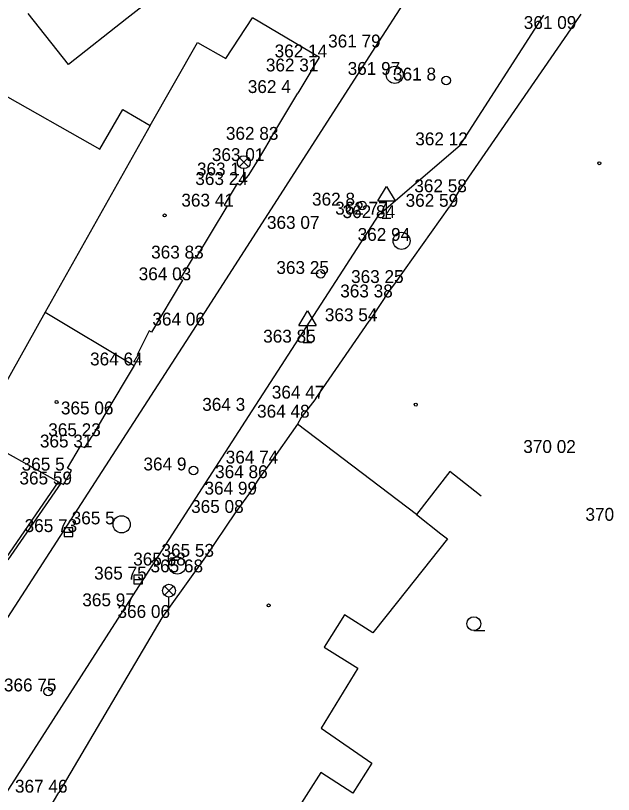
# Model space of a CAD drawing. Extents: x -688316 to -688024, y -973785 to -973591.
# Drawn here: x -688087.33 to -688052.43, y -973675.68 to -973630.22 of the extents above; entities that cross this region are included whole.
import ezdxf

# ---------------------------------------------------------------- set-up
doc = ezdxf.new("R2010")
doc.units = 0
for name, color, linetype in [('Vrstva 10', 7, 'Continuous'), ('Vrstva 27', 7, 'Continuous'), ('Vrstva 28_Verejne osvetleni', 7, 'Continuous'), ('Vrstva 3', 7, 'Continuous'), ('Vrstva 33', 7, 'Continuous'), ('Vrstva 34', 7, 'Continuous'), ('Vrstva 36', 7, 'Continuous'), ('Vrstva 5', 7, 'Continuous'), ('Vrstva 58', 7, 'Continuous'), ('Vrstva 6', 7, 'Continuous'), ('Vrstva 9', 7, 'Continuous')]:
    doc.layers.add(name, color=color, linetype=linetype)

# ---------------------------------------------------------------- blocks, each defined once
blk = doc.blocks.new('B_NESP')
at = {"layer": 'Vrstva 58'}
blk.add_circle((0, 0), 0.875, dxfattribs=at)
blk = doc.blocks.new('DZ')
at = {"layer": 'Vrstva 34'}
for p, q in [((-5, 10), (0, 18.5)), ((0, 18.5), (5, 10)), ((-5, 10), (5, 10)), ((0, 0), (0, 10)), ((-2.49, 0), (2.49, 0))]:
    blk.add_line(p, q, dxfattribs=at)
blk = doc.blocks.new('LAO')
at = {"layer": 'Vrstva 33'}
for p, q in [((-2.65, 14.16), (2.65, 8.85)), ((-2.65, 8.85), (2.65, 14.16)), ((0, 0), (0, 7.75))]:
    blk.add_line(p, q, dxfattribs=at)
blk.add_circle((0, 11.5), 3.75, dxfattribs=at)
blk = doc.blocks.new('SAK')
at = {"layer": 'Vrstva 27'}
blk.add_circle((0, 0), 5, dxfattribs=at)
blk = doc.blocks.new('SV')
at = {"layer": 'Vrstva 28_Verejne osvetleni'}
blk.add_circle((0, 0), 2.5, dxfattribs=at)
blk = doc.blocks.new('ZAHRA')
at = {"layer": 'Vrstva 36'}
blk.add_line((-0.12, 0), (6.38, 0.03), dxfattribs=at)
blk.add_circle((-0.12, 4.03), 4.03, dxfattribs=at)
blk = doc.blocks.new('VP')
at = {"layer": 'Vrstva 27'}
blk.add_line((-2.5, 0), (2.5, 0), dxfattribs=at)
blk.add_lwpolyline([(-2.5, -2.5), (2.5, -2.5), (2.5, 2.5), (-2.5, 2.5)], close=True, dxfattribs=at)

msp = doc.modelspace()

# ---------------------------------------------------------------- linework, layer by layer
at = {"layer": 'Vrstva 10'}
for p, q in [((-688066.34, -973632.08), (-688059.63, -973621.62)), ((-688061.38, -973637.79), (-688056.49, -973630.19)), ((-688076.78, -973648.31), (-688066.34, -973632.08)), ((-688066.11, -973641.84), (-688061.38, -973637.79)), ((-688073.52, -973653.29), (-688066.11, -973641.84)), ((-688089.26, -973667.62), (-688076.78, -973648.31)), ((-688080.87, -973664.7), (-688073.52, -973653.29)), ((-688087.77, -973662), (-688084.68, -973657.51)), ((-688088.66, -973676.81), (-688080.87, -973664.7))]:
    msp.add_line(p, q, dxfattribs=at)
at = {"layer": 'Vrstva 5'}
for p, q in [((-688079.01, -973628.96), (-688080.84, -973630.4)), ((-688084.25, -973633.08), (-688086.6, -973630.1)), ((-688080.84, -973630.4), (-688084.25, -973633.08)), ((-688075.06, -973632.73), (-688073.51, -973630.36)), ((-688054.92, -973631), (-688061.49, -973640.53)), ((-688079.48, -973636.64), (-688076.72, -973631.79)), ((-688076.72, -973631.79), (-688075.06, -973632.73)), ((-688089.95, -973633.75), (-688082.42, -973638.02)), ((-688072.49, -973637.47), (-688070.86, -973634.74)), ((-688082.42, -973638.02), (-688081.07, -973635.7)), ((-688081.07, -973635.7), (-688079.48, -973636.64)), ((-688085.61, -973647.54), (-688080.41, -973650.64)), ((-688069.81, -973652.58), (-688066.69, -973648.06)), ((-688063.93, -973659.35), (-688070.88, -973654.07)), ((-688061.98, -973656.84), (-688063.93, -973659.35)), ((-688060.53, -973657.98), (-688061.98, -973656.84)), ((-688060.15, -973658.28), (-688060.53, -973657.98)), ((-688063.93, -973659.35), (-688062.5, -973660.47)), ((-688062.5, -973660.47), (-688062.12, -973660.76)), ((-688062.12, -973660.76), (-688065.04, -973664.45)), ((-688065.04, -973664.45), (-688066.47, -973666.25)), ((-688067.35, -973668.31), (-688069.49, -973671.81)), ((-688069.49, -973671.81), (-688066.53, -973673.86)), ((-688066.53, -973673.86), (-688067.65, -973675.61)), ((-688069.52, -973674.41), (-688070.24, -973675.54)), ((-688067.65, -973675.61), (-688069.52, -973674.41)), ((-688070.24, -973675.54), (-688071.06, -973676.81))]:
    msp.add_line(p, q, dxfattribs=at)
for points in [[(-688070.09, -973633.48), (-688069.59, -973632.66), (-688073.51, -973630.36)], [(-688079.48, -973636.64), (-688085.61, -973647.54), (-688089.66, -973654.75)], [(-688073.23, -973638.71), (-688073.75, -973639.55), (-688074.25, -973640.11), (-688074.39, -973640.02), (-688075.15, -973641.29), (-688075.01, -973641.37), (-688076.83, -973644.4), (-688076.97, -973644.33), (-688077.73, -973645.58), (-688077.58, -973645.67), (-688079.39, -973648.7), (-688079.53, -973648.63), (-688080.23, -973650.02), (-688080.09, -973650.1), (-688080.41, -973650.64), (-688082.12, -973653.5)], [(-688065.78, -973646.67), (-688065.6, -973646.42), (-688065.16, -973645.83), (-688062, -973641.38)], [(-688099.29, -973649.41), (-688099.15, -973649.49), (-688090.01, -973654.56), (-688089.66, -973654.75), (-688084.82, -973657.44), (-688084.68, -973657.51), (-688084.54, -973657.59), (-688084.06, -973656.78), (-688084.31, -973656.63), (-688083.55, -973655.36), (-688083.28, -973655.43), (-688082.86, -973654.77)], [(-688070.67, -973653.69), (-688070.88, -973654.07), (-688072.5, -973656.37)], [(-688073.12, -973657.22), (-688073.74, -973658.18), (-688074.52, -973659.25), (-688076.25, -973661.81)], [(-688076.88, -973662.72), (-688078.8, -973665.38), (-688084.8, -973675.58)], [(-688066.47, -973666.25), (-688068.13, -973665.21), (-688069.31, -973667.08), (-688067.35, -973668.31)]]:
    msp.add_lwpolyline(points, dxfattribs=at)
at = {"layer": 'Vrstva 6'}
for p, q in [((-688054.34, -973630.14), (-688054.92, -973631)), ((-688070.09, -973633.48), (-688070.86, -973634.74)), ((-688072.49, -973637.47), (-688073.23, -973638.71)), ((-688061.49, -973640.53), (-688062, -973641.38)), ((-688065.78, -973646.67), (-688066.69, -973648.06)), ((-688069.81, -973652.58), (-688070.67, -973653.69)), ((-688082.12, -973653.5), (-688082.86, -973654.77)), ((-688072.5, -973656.37), (-688073.12, -973657.22)), ((-688076.25, -973661.81), (-688076.88, -973662.72)), ((-688085.38, -973676.52), (-688084.8, -973675.58))]:
    msp.add_line(p, q, dxfattribs=at)
at = {"layer": 'Vrstva 9'}
msp.add_lwpolyline([(-688088.82, -973663.21), (-688087.9, -973661.91), (-688084.82, -973657.44)], dxfattribs=at)

# ---------------------------------------------------------------- block references
at = {"layer": 'Vrstva 27', "xscale": 0.1, "yscale": 0.10000000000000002}
for name, p in [('SAK', (-688065.2, -973633.68)), ('SAK', (-688064.8, -973643.37)), ('SAK', (-688081.14, -973659.92)), ('VP', (-688084.24, -973660.37)), ('SAK', (-688077.89, -973662.32)), ('VP', (-688080.18, -973663.14))]:
    msp.add_blockref(name, p, dxfattribs=at)
at = {"layer": 'Vrstva 28_Verejne osvetleni', "xscale": 0.1, "yscale": 0.10000000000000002}
for p in [(-688062.2, -973634.01), (-688067.11, -973641.31), (-688069.52, -973645.3), (-688076.95, -973656.77), (-688085.43, -973669.67)]:
    msp.add_blockref('SV', p, dxfattribs=at)
at = {"layer": 'Vrstva 33', "xscale": 0.1, "yscale": 0.10000000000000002}
for p in [(-688074.01, -973639.93), (-688078.38, -973664.94)]:
    msp.add_blockref('LAO', p, dxfattribs=at)
at = {"layer": 'Vrstva 34', "xscale": 0.1, "yscale": 0.10000000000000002}
for p in [(-688065.68, -973642.04), (-688065.68, -973642.04), (-688065.68, -973642.04), (-688065.68, -973642.04), (-688070.29, -973649.31), (-688070.29, -973649.31), (-688070.29, -973649.31), (-688070.29, -973649.31)]:
    msp.add_blockref('DZ', p, dxfattribs=at)
at = {"layer": 'Vrstva 36', "xscale": 0.1, "yscale": 0.10000000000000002}
msp.add_blockref('ZAHRA', (-688060.57, -973666.12), dxfattribs=at)
at = {"layer": 'Vrstva 58', "xscale": 0.1, "yscale": 0.10000000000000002}
for p in [(-688053.26, -973638.84), (-688053.26, -973638.84), (-688053.26, -973638.84), (-688053.26, -973638.84), (-688078.63, -973641.89), (-688078.63, -973641.89), (-688078.63, -973641.89), (-688078.63, -973641.89), (-688084.94, -973652.78), (-688084.94, -973652.78), (-688084.94, -973652.78), (-688084.94, -973652.78), (-688063.97, -973652.93), (-688063.97, -973652.93), (-688063.97, -973652.93), (-688063.97, -973652.93), (-688072.56, -973664.65), (-688072.56, -973664.65), (-688072.56, -973664.65), (-688072.56, -973664.65)]:
    msp.add_blockref('B_NESP', p, dxfattribs=at)

# ---------------------------------------------------------------- texts
at = {"layer": 'Vrstva 3'}
for s, p in [('361 09 ', (-688057.668, -973631)), ('361 09 ', (-688057.668, -973631)), ('361 09 ', (-688057.668, -973631)), ('361 09 ', (-688057.668, -973631)), ('361 09 ', (-688057.668, -973631)), ('361 09 ', (-688057.668, -973631)), ('361 09 ', (-688057.668, -973631)), ('361 79 ', (-688069.088, -973632.08)), ('361 79 ', (-688069.088, -973632.08)), ('361 79 ', (-688069.088, -973632.08)), ('361 79 ', (-688069.088, -973632.08)), ('361 79 ', (-688069.088, -973632.08)), ('361 79 ', (-688069.088, -973632.08)), ('361 79 ', (-688069.088, -973632.08)), ('362 14 ', (-688072.211, -973632.66)), ('362 14 ', (-688072.211, -973632.66)), ('362 14 ', (-688072.211, -973632.66)), ('362 14 ', (-688072.211, -973632.66)), ('362 14 ', (-688072.211, -973632.66)), ('362 14 ', (-688072.211, -973632.66)), ('362 14 ', (-688072.211, -973632.66)), ('362 31 ', (-688072.723, -973633.48)), ('362 31 ', (-688072.723, -973633.48)), ('362 31 ', (-688072.723, -973633.48)), ('362 31 ', (-688072.723, -973633.48)), ('362 31 ', (-688072.723, -973633.48)), ('362 31 ', (-688072.723, -973633.48)), ('362 31 ', (-688072.723, -973633.48)), ('361 97 ', (-688067.948, -973633.68)), ('361 97 ', (-688067.948, -973633.68)), ('361 97 ', (-688067.948, -973633.68)), ('361 97 ', (-688067.948, -973633.68)), ('361 97 ', (-688067.948, -973633.68)), ('361 97 ', (-688067.948, -973633.68)), ('361 97 ', (-688067.948, -973633.68)), ('361 8  ', (-688065.299, -973634.01)), ('361 8  ', (-688065.299, -973634.01)), ('361 8  ', (-688065.299, -973634.01)), ('361 8  ', (-688065.299, -973634.01)), ('361 8  ', (-688065.299, -973634.01)), ('361 8  ', (-688065.299, -973634.01)), ('361 8  ', (-688065.299, -973634.01)), ('362 4  ', (-688073.777, -973634.74)), ('362 4  ', (-688073.777, -973634.74)), ('362 4  ', (-688073.777, -973634.74)), ('362 4  ', (-688073.777, -973634.74)), ('362 4  ', (-688073.777, -973634.74)), ('362 4  ', (-688073.777, -973634.74)), ('362 4  ', (-688073.777, -973634.74)), ('362 83 ', (-688075.056, -973637.47)), ('362 83 ', (-688075.056, -973637.47)), ('362 83 ', (-688075.056, -973637.47)), ('362 83 ', (-688075.056, -973637.47)), ('362 83 ', (-688075.056, -973637.47)), ('362 83 ', (-688075.056, -973637.47)), ('362 83 ', (-688075.056, -973637.47)), ('362 12 ', (-688064.001, -973637.79)), ('362 12 ', (-688064.001, -973637.79)), ('362 12 ', (-688064.001, -973637.79)), ('362 12 ', (-688064.001, -973637.79)), ('362 12 ', (-688064.001, -973637.79)), ('362 12 ', (-688064.001, -973637.79)), ('362 12 ', (-688064.001, -973637.79)), ('363 01 ', (-688075.875, -973638.71)), ('363 01 ', (-688075.875, -973638.71)), ('363 01 ', (-688075.875, -973638.71)), ('363 01 ', (-688075.875, -973638.71)), ('363 01 ', (-688075.875, -973638.71)), ('363 01 ', (-688075.875, -973638.71)), ('363 01 ', (-688075.875, -973638.71)), ('363 1  ', (-688076.746, -973639.55)), ('363 1  ', (-688076.746, -973639.55)), ('363 1  ', (-688076.746, -973639.55)), ('363 1  ', (-688076.746, -973639.55)), ('363 1  ', (-688076.746, -973639.55)), ('363 1  ', (-688076.746, -973639.55)), ('363 1  ', (-688076.746, -973639.55)), ('363 24 ', (-688076.839, -973640.11)), ('363 24 ', (-688076.839, -973640.11)), ('363 24 ', (-688076.839, -973640.11)), ('363 24 ', (-688076.839, -973640.11)), ('363 24 ', (-688076.839, -973640.11)), ('363 24 ', (-688076.839, -973640.11)), ('363 24 ', (-688076.839, -973640.11)), ('362 58 ', (-688064.056, -973640.53)), ('362 58 ', (-688064.056, -973640.53)), ('362 58 ', (-688064.056, -973640.53)), ('362 58 ', (-688064.056, -973640.53)), ('362 58 ', (-688064.056, -973640.53)), ('362 58 ', (-688064.056, -973640.53)), ('362 58 ', (-688064.056, -973640.53)), ('362 8  ', (-688070.027, -973641.31)), ('362 8  ', (-688070.027, -973641.31)), ('362 8  ', (-688070.027, -973641.31)), ('362 8  ', (-688070.027, -973641.31)), ('362 8  ', (-688070.027, -973641.31)), ('362 8  ', (-688070.027, -973641.31)), ('362 8  ', (-688070.027, -973641.31)), ('363 41 ', (-688077.655, -973641.37)), ('363 41 ', (-688077.655, -973641.37)), ('363 41 ', (-688077.655, -973641.37)), ('363 41 ', (-688077.655, -973641.37)), ('363 41 ', (-688077.655, -973641.37)), ('363 41 ', (-688077.655, -973641.37)), ('363 41 ', (-688077.655, -973641.37)), ('362 59 ', (-688064.566, -973641.38)), ('362 59 ', (-688064.566, -973641.38)), ('362 59 ', (-688064.566, -973641.38)), ('362 59 ', (-688064.566, -973641.38)), ('362 59 ', (-688064.566, -973641.38)), ('362 59 ', (-688064.566, -973641.38)), ('362 59 ', (-688064.566, -973641.38)), ('362 77 ', (-688068.676, -973641.84)), ('362 77 ', (-688068.676, -973641.84)), ('362 77 ', (-688068.676, -973641.84)), ('362 77 ', (-688068.676, -973641.84)), ('362 77 ', (-688068.676, -973641.84)), ('362 77 ', (-688068.676, -973641.84)), ('362 77 ', (-688068.676, -973641.84)), ('362 84 ', (-688068.246, -973642.04)), ('362 84 ', (-688068.246, -973642.04)), ('362 84 ', (-688068.246, -973642.04)), ('362 84 ', (-688068.246, -973642.04)), ('362 84 ', (-688068.246, -973642.04)), ('362 84 ', (-688068.246, -973642.04)), ('362 84 ', (-688068.246, -973642.04)), ('363 07 ', (-688072.659, -973642.67)), ('363 07 ', (-688072.659, -973642.67)), ('363 07 ', (-688072.659, -973642.67)), ('363 07 ', (-688072.659, -973642.67)), ('363 07 ', (-688072.659, -973642.67)), ('363 07 ', (-688072.659, -973642.67)), ('363 07 ', (-688072.659, -973642.67)), ('362 94 ', (-688067.366, -973643.37)), ('362 94 ', (-688067.366, -973643.37)), ('362 94 ', (-688067.366, -973643.37)), ('362 94 ', (-688067.366, -973643.37)), ('362 94 ', (-688067.366, -973643.37)), ('362 94 ', (-688067.366, -973643.37)), ('362 94 ', (-688067.366, -973643.37)), ('363 83 ', (-688079.419, -973644.4)), ('363 83 ', (-688079.419, -973644.4)), ('363 83 ', (-688079.419, -973644.4)), ('363 83 ', (-688079.419, -973644.4)), ('363 83 ', (-688079.419, -973644.4)), ('363 83 ', (-688079.419, -973644.4)), ('363 83 ', (-688079.419, -973644.4)), ('363 25 ', (-688072.109, -973645.3)), ('363 25 ', (-688072.109, -973645.3)), ('363 25 ', (-688072.109, -973645.3)), ('363 25 ', (-688072.109, -973645.3)), ('363 25 ', (-688072.109, -973645.3)), ('363 25 ', (-688072.109, -973645.3)), ('363 25 ', (-688072.109, -973645.3)), ('364 03 ', (-688080.146, -973645.67)), ('364 03 ', (-688080.146, -973645.67)), ('364 03 ', (-688080.146, -973645.67)), ('364 03 ', (-688080.146, -973645.67)), ('364 03 ', (-688080.146, -973645.67)), ('364 03 ', (-688080.146, -973645.67)), ('364 03 ', (-688080.146, -973645.67)), ('363 25 ', (-688067.749, -973645.83)), ('363 25 ', (-688067.749, -973645.83)), ('363 25 ', (-688067.749, -973645.83)), ('363 25 ', (-688067.749, -973645.83)), ('363 25 ', (-688067.749, -973645.83)), ('363 25 ', (-688067.749, -973645.83)), ('363 25 ', (-688067.749, -973645.83)), ('363 38 ', (-688068.381, -973646.67)), ('363 38 ', (-688068.381, -973646.67)), ('363 38 ', (-688068.381, -973646.67)), ('363 38 ', (-688068.381, -973646.67)), ('363 38 ', (-688068.381, -973646.67)), ('363 38 ', (-688068.381, -973646.67)), ('363 38 ', (-688068.381, -973646.67)), ('363 54 ', (-688069.279, -973648.06)), ('363 54 ', (-688069.279, -973648.06)), ('363 54 ', (-688069.279, -973648.06)), ('363 54 ', (-688069.279, -973648.06)), ('363 54 ', (-688069.279, -973648.06)), ('363 54 ', (-688069.279, -973648.06)), ('363 54 ', (-688069.279, -973648.06)), ('364 06 ', (-688079.346, -973648.31)), ('364 06 ', (-688079.346, -973648.31)), ('364 06 ', (-688079.346, -973648.31)), ('364 06 ', (-688079.346, -973648.31)), ('364 06 ', (-688079.346, -973648.31)), ('364 06 ', (-688079.346, -973648.31)), ('364 06 ', (-688079.346, -973648.31)), ('363 85 ', (-688072.879, -973649.31)), ('363 85 ', (-688072.879, -973649.31)), ('363 85 ', (-688072.879, -973649.31)), ('363 85 ', (-688072.879, -973649.31)), ('363 85 ', (-688072.879, -973649.31)), ('363 85 ', (-688072.879, -973649.31)), ('363 85 ', (-688072.879, -973649.31)), ('364 64 ', (-688082.985, -973650.64)), ('364 64 ', (-688082.985, -973650.64)), ('364 64 ', (-688082.985, -973650.64)), ('364 64 ', (-688082.985, -973650.64)), ('364 64 ', (-688082.985, -973650.64)), ('364 64 ', (-688082.985, -973650.64)), ('364 64 ', (-688082.985, -973650.64)), ('364 47 ', (-688072.376, -973652.58)), ('364 47 ', (-688072.376, -973652.58)), ('364 47 ', (-688072.376, -973652.58)), ('364 47 ', (-688072.376, -973652.58)), ('364 47 ', (-688072.376, -973652.58)), ('364 47 ', (-688072.376, -973652.58)), ('364 47 ', (-688072.376, -973652.58)), ('365 06 ', (-688084.686, -973653.5)), ('365 06 ', (-688084.686, -973653.5)), ('365 06 ', (-688084.686, -973653.5)), ('365 06 ', (-688084.686, -973653.5)), ('365 06 ', (-688084.686, -973653.5)), ('365 06 ', (-688084.686, -973653.5)), ('365 06 ', (-688084.686, -973653.5)), ('364 3  ', (-688076.437, -973653.29)), ('364 3  ', (-688076.437, -973653.29)), ('364 3  ', (-688076.437, -973653.29)), ('364 3  ', (-688076.437, -973653.29)), ('364 3  ', (-688076.437, -973653.29)), ('364 3  ', (-688076.437, -973653.29)), ('364 3  ', (-688076.437, -973653.29)), ('364 48 ', (-688073.236, -973653.69)), ('364 48 ', (-688073.236, -973653.69)), ('364 48 ', (-688073.236, -973653.69)), ('364 48 ', (-688073.236, -973653.69)), ('364 48 ', (-688073.236, -973653.69)), ('364 48 ', (-688073.236, -973653.69)), ('364 48 ', (-688073.236, -973653.69)), ('365 23 ', (-688085.426, -973654.77)), ('365 23 ', (-688085.426, -973654.77)), ('365 23 ', (-688085.426, -973654.77)), ('365 23 ', (-688085.426, -973654.77)), ('365 23 ', (-688085.426, -973654.77)), ('365 23 ', (-688085.426, -973654.77)), ('365 23 ', (-688085.426, -973654.77)), ('365 31 ', (-688085.913, -973655.43)), ('365 31 ', (-688085.913, -973655.43)), ('365 31 ', (-688085.913, -973655.43)), ('365 31 ', (-688085.913, -973655.43)), ('365 31 ', (-688085.913, -973655.43)), ('365 31 ', (-688085.913, -973655.43)), ('365 31 ', (-688085.913, -973655.43)), ('370 02 ', (-688057.697, -973655.75)), ('370 02 ', (-688057.697, -973655.75)), ('370 02 ', (-688057.697, -973655.75)), ('370 02 ', (-688057.697, -973655.75)), ('370 02 ', (-688057.697, -973655.75)), ('370 02 ', (-688057.697, -973655.75)), ('370 02 ', (-688057.697, -973655.75)), ('364 74 ', (-688075.066, -973656.37)), ('364 74 ', (-688075.066, -973656.37)), ('364 74 ', (-688075.066, -973656.37)), ('364 74 ', (-688075.066, -973656.37)), ('364 74 ', (-688075.066, -973656.37)), ('364 74 ', (-688075.066, -973656.37)), ('364 74 ', (-688075.066, -973656.37)), ('365 5  ', (-688086.977, -973656.78)), ('365 5  ', (-688086.977, -973656.78)), ('365 5  ', (-688086.977, -973656.78)), ('365 5  ', (-688086.977, -973656.78)), ('365 5  ', (-688086.977, -973656.78)), ('365 5  ', (-688086.977, -973656.78)), ('365 5  ', (-688086.977, -973656.78)), ('364 9  ', (-688079.867, -973656.77)), ('364 9  ', (-688079.867, -973656.77)), ('364 9  ', (-688079.867, -973656.77)), ('364 9  ', (-688079.867, -973656.77)), ('364 9  ', (-688079.867, -973656.77)), ('364 9  ', (-688079.867, -973656.77)), ('364 9  ', (-688079.867, -973656.77)), ('364 86 ', (-688075.686, -973657.22)), ('364 86 ', (-688075.686, -973657.22)), ('364 86 ', (-688075.686, -973657.22)), ('364 86 ', (-688075.686, -973657.22)), ('364 86 ', (-688075.686, -973657.22)), ('364 86 ', (-688075.686, -973657.22)), ('364 86 ', (-688075.686, -973657.22)), ('365 59 ', (-688087.106, -973657.59)), ('365 59 ', (-688087.106, -973657.59)), ('365 59 ', (-688087.106, -973657.59)), ('365 59 ', (-688087.106, -973657.59)), ('365 59 ', (-688087.106, -973657.59)), ('365 59 ', (-688087.106, -973657.59)), ('365 59 ', (-688087.106, -973657.59)), ('364 99 ', (-688076.306, -973658.18)), ('364 99 ', (-688076.306, -973658.18)), ('364 99 ', (-688076.306, -973658.18)), ('364 99 ', (-688076.306, -973658.18)), ('364 99 ', (-688076.306, -973658.18)), ('364 99 ', (-688076.306, -973658.18)), ('364 99 ', (-688076.306, -973658.18)), ('365 08 ', (-688077.086, -973659.25)), ('365 08 ', (-688077.086, -973659.25)), ('365 08 ', (-688077.086, -973659.25)), ('365 08 ', (-688077.086, -973659.25)), ('365 08 ', (-688077.086, -973659.25)), ('365 08 ', (-688077.086, -973659.25)), ('365 08 ', (-688077.086, -973659.25)), ('365 5  ', (-688084.057, -973659.92)), ('365 5  ', (-688084.057, -973659.92)), ('365 5  ', (-688084.057, -973659.92)), ('365 5  ', (-688084.057, -973659.92)), ('365 5  ', (-688084.057, -973659.92)), ('365 5  ', (-688084.057, -973659.92)), ('365 5  ', (-688084.057, -973659.92)), ('370    ', (-688054.068, -973659.71)), ('370    ', (-688054.068, -973659.71)), ('370    ', (-688054.068, -973659.71)), ('370    ', (-688054.068, -973659.71)), ('370    ', (-688054.068, -973659.71)), ('370    ', (-688054.068, -973659.71)), ('370    ', (-688054.068, -973659.71)), ('365 73 ', (-688086.806, -973660.37)), ('365 73 ', (-688086.806, -973660.37)), ('365 73 ', (-688086.806, -973660.37)), ('365 73 ', (-688086.806, -973660.37)), ('365 73 ', (-688086.806, -973660.37)), ('365 73 ', (-688086.806, -973660.37)), ('365 73 ', (-688086.806, -973660.37)), ('365 53 ', (-688078.816, -973661.81)), ('365 53 ', (-688078.816, -973661.81)), ('365 53 ', (-688078.816, -973661.81)), ('365 53 ', (-688078.816, -973661.81)), ('365 53 ', (-688078.816, -973661.81)), ('365 53 ', (-688078.816, -973661.81)), ('365 53 ', (-688078.816, -973661.81)), ('365 68 ', (-688080.465, -973662.32)), ('365 68 ', (-688080.465, -973662.32)), ('365 68 ', (-688080.465, -973662.32)), ('365 68 ', (-688080.465, -973662.32)), ('365 68 ', (-688080.465, -973662.32)), ('365 68 ', (-688080.465, -973662.32)), ('365 68 ', (-688080.465, -973662.32)), ('365 68 ', (-688079.455, -973662.72)), ('365 68 ', (-688079.455, -973662.72)), ('365 68 ', (-688079.455, -973662.72)), ('365 68 ', (-688079.455, -973662.72)), ('365 68 ', (-688079.455, -973662.72)), ('365 68 ', (-688079.455, -973662.72)), ('365 68 ', (-688079.455, -973662.72)), ('365 75 ', (-688082.746, -973663.14)), ('365 75 ', (-688082.746, -973663.14)), ('365 75 ', (-688082.746, -973663.14)), ('365 75 ', (-688082.746, -973663.14)), ('365 75 ', (-688082.746, -973663.14)), ('365 75 ', (-688082.746, -973663.14)), ('365 75 ', (-688082.746, -973663.14)), ('365 97 ', (-688083.436, -973664.7)), ('365 97 ', (-688083.436, -973664.7)), ('365 97 ', (-688083.436, -973664.7)), ('365 97 ', (-688083.436, -973664.7)), ('365 97 ', (-688083.436, -973664.7)), ('365 97 ', (-688083.436, -973664.7)), ('365 97 ', (-688083.436, -973664.7)), ('366 06 ', (-688081.383, -973665.38)), ('366 06 ', (-688081.383, -973665.38)), ('366 06 ', (-688081.383, -973665.38)), ('366 06 ', (-688081.383, -973665.38)), ('366 06 ', (-688081.383, -973665.38)), ('366 06 ', (-688081.383, -973665.38)), ('366 06 ', (-688081.383, -973665.38)), ('366 75 ', (-688088.013, -973669.67)), ('366 75 ', (-688088.013, -973669.67)), ('366 75 ', (-688088.013, -973669.67)), ('366 75 ', (-688088.013, -973669.67)), ('366 75 ', (-688088.013, -973669.67)), ('366 75 ', (-688088.013, -973669.67)), ('366 75 ', (-688088.013, -973669.67)), ('367 46 ', (-688087.366, -973675.58)), ('367 46 ', (-688087.366, -973675.58)), ('367 46 ', (-688087.366, -973675.58)), ('367 46 ', (-688087.366, -973675.58)), ('367 46 ', (-688087.366, -973675.58)), ('367 46 ', (-688087.366, -973675.58)), ('367 46 ', (-688087.366, -973675.58))]:
    msp.add_text(s, height=0.75, dxfattribs=at).set_placement(p)

doc.saveas('drawing.dxf')
